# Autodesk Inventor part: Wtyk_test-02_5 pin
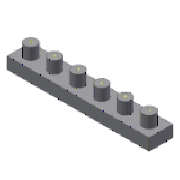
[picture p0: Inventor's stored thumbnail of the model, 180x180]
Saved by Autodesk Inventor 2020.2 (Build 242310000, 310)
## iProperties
Manager: www.cadconsulting.pl
Company: Fabian Stasiak CAD Consulting
Created: 2014-09
Part Number: Wtyk_test-02_5 pin
Material: Ogólny
Document SubType Name: Modeling
Designer: F.Stasiak
Language: pl-PL
Size Designation: 5-Wtyk_test-02_5 pin
Categories: <MemberInstance><Categories><Category DisplayName="Kable i wiązki przewodów" InternalName="e4a7e005-5e42-4d16-b293-125e7f0d0512" Mnemonic="CABLEANDHARNESS"><Cat
Density: 1 g/cm^3
Appearance: Domyślna
Catalog Web Link: www.expertbooks.pl
IsCustomPart: 0
Author: F.Stasiak
Subject: Zbiór ćwiczeń. Autodesk Inventor 2020. Kurs Professional
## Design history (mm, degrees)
sketch "Szkic1"
  geometry: L1 (0, 0)-(60, 0); L2 (0, 5)-(50, 5); L3 (50, 5)-(50, -5); L4 (50, -5)-(0, -5); L5 (0, -5)-(0, 5); 7 further points
  constraints: 10 end point, 2 horizontal, 2 parallel, 1 coincident, 1 midpoint, 1 perpendicular
  dimensions: "d0" = 10 distance of point (15, 0) point (5, 0); "d1" = 10 distance of point (25, 0) point (15, 0) (= d0); "d2" = 10 distance of point (35, 0) point (25, 0) (= d0); "d3" = 10 distance of point (45, 0) point (35, 0) (= d0); "d4" = 10 distance of point (45, 0) point (55, 0) (= d0); "d16" = 5 distance of point (5, 0) L1.start; "d17" = 5 distance of point (55, 0) L1.end (= d16); "d18" = 10 distance of L4.end L2.start; "d19" = 50 distance of L3.end L4.end (= LPINÓW)
node "Oś konstrukcyjna1"
node "Oś konstrukcyjna2"
node "Oś konstrukcyjna3"
node "Oś konstrukcyjna4"
node "Oś konstrukcyjna5"
node "Oś konstrukcyjna6"
extrude "Wyciągnięcie proste3" new body sketch "Szkic1" distance "d20" = 5; taper "d21" = 0 deg
sketch "Szkic3"
  geometry: C1 r 2.5 at (5, 0); 2 further points
  constraints: 1 centre point, 1 coincident
  dimensions: "d22" = 5 diameter of C1
extrude "Wyciągnięcie proste4" join sketch "Szkic3" distance "d23" = 5; taper "d24" = 0 deg
pattern_linear "Szyk prostokątny2" dims "d27" = 10
node "Płaszczyzna konstrukcyjna1"
node "Punkt konstrukcyjny2"
node "Punkt konstrukcyjny3"
node "Punkt konstrukcyjny4"
node "Punkt konstrukcyjny5"
node "Punkt konstrukcyjny6"
node "Punkt konstrukcyjny7"
node "1"
node "2"
node "3"
node "4"
node "5"
node "6"
node "Bryła2"
other parameters: "LPINÓW" = 50 [user parameter; used in 2 equation terms]
